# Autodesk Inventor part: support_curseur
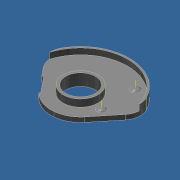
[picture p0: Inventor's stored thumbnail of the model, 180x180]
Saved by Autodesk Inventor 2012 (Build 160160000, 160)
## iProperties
Created: 2011-07
Part Number: support_curseur
Document SubType Name: Modeling
Designer: didierf
Density: 1.4 g/cm^3
Material: PVC-U
Mass: 0.16648 g
Surface Area: 3.90351 cm^2
Volume: 0.118915 cm^3
Author: didierf
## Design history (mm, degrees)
sketch "Esquisse3"
  geometry: L1 (-14.379, 11.345)-(1.25, 18.566); L2 (1.25, 18.566)-(10.479, -1.409); L3 (10.479, -1.409)-(-5.149, -8.63); L4 (-5.149, -8.63)-(-14.379, 11.345); L5 (4.506, -11.411)-(4.506, -32.563); 1 other entity
  constraints: 2 end point, 1 vertical, 2 other
  dimensions: "d19" = 17.216 distance of L1.start L1.end; "d84" = 24.7991 deg angle of L5 L4
  node "Image2"
sketch "tracé"
  geometry: L1 (3.886, -3.147)-(6.941, 0.626); L2 (0, -41.976)-(0, 8.25); L3 (-3.534, -3.184)-(-5.423, -0.851); L4 (-5.774, -0.814)-(-6.941, 0.626); L5 (0, 0)-(-3.552, -3.519); C1 r 2.5 at (0, 0); C2 r 0.5 at (4.25, -0.7); C3 r 0.5 at (4.25, 5.1); C4 r 2.95 at (0, 0); C5 r 1 at (3, 4); A1 r 5 centre (0, 0) between (-3.552, -3.519) and (3.886, -3.147); A2 r 8.25 centre (0, 0) between (7.243, 3.95) and (-7.243, 3.95); A3 r 3 centre (-4.609, 2.514) between (-7.243, 3.95) and (-6.941, 0.626); A4 r 3 centre (4.609, 2.514) between (6.941, 0.626) and (7.243, 3.95); A5 r 0.25 centre (-3.728, -3.341) between (-3.552, -3.519) and (-3.534, -3.184); A6 r 0.25 centre (-5.617, -1.009) between (-5.423, -0.851) and (-5.774, -0.814); A7 r 7.95 centre (0, 0) between (7.603, 2.323) and (-7.603, 2.323); 1 further point
  constraints: 17 point on circle, 12 centre point, 10 end point, 9 tangent, 5 coincident, 1 parallel, 1 point on line, 1 vertical
  dimensions: "d53" = 10 diameter of A1; "d54" = 5 diameter of C1; "d57" = 8.25 radius of A2; "d60" = 6 diameter of A3; "d61" = 6 diameter of A4; "d66" = 78 deg angle of L1 L4; "d67" = 0.25 radius of A5; "d68" = 0.25 radius of A6; "d69" = 0.25 distance between parallel lines of L4 L3; "d70" = 3.5 distance of L4.start L5.end; "d71" = 39 deg angle of L1 L2 (derived); "d104" = 1 diameter of C2; "d105" = 1 diameter of C3; "d106" = 4.25 horizontal distance of C2.centre point (0, 0); "d107" = 0.7 vertical distance of C2.centre point (0, 0); "d108" = 5.8 distance of C2.centre C3.centre; "d109" = 4.25 horizontal distance of C3.centre point (0, 0) (derived); "d110" = 0.3 radial gap between concentric circles of A7 A2; "d114" = 5.9 diameter of C4; "d115" = 2 diameter of C5; "d117" = 3 distance from line of C5.centre L2; "d120" = 4 vertical distance of C5.centre point (0, 0)
extrude "embase" new body sketch "tracé" distance "d122" = 0.8; taper "d123" = 0 deg
extrude "bossage central" join sketch "tracé" distance "d124" = 1.2; taper "d125" = 0 deg
extrude "plotSertissage1" join sketch "tracé" distance "d126" = 1; taper "d127" = 0 deg
extrude "plotSertissage2" join sketch "tracé" distance "d128" = 0.1; taper "d129" = 0 deg
node "Plan de construction1"
  node "Axe de construction1"
  node "Axe de construction2"
sketch "sertissage"
  geometry: L1 (-1.2, 5.8)-(1.6, 5.8) reference; L2 (0.1, 6.3)-(0.1, 5.3) reference; L3 (0.4, 4.925)-(0.4, 6.54); L4 (0.1, 5.05)-(0.1, 6.55); L5 (0.1, 0.5)-(0.1, -0.5) reference; L6 (0.4, 1.009)-(0.4, -1.186); L7 (-1.2, 0)-(1.6, 0) reference; L8 (0.1, 0)-(0.1, -0.75); L9 (0.1, 0)-(0.1, 0.75); L10 (0.4, 5.8)-(0.1, 5.8); L11 (0.4, 0)-(0.1, 0); A1 r 1.088 centre (-0.687, 5.8) between (0.1, 5.05) and (0.4, 5.8); A2 r 1.088 centre (-0.688, 0) between (0.1, -0.75) and (0.4, 0)
  constraints: 14 end point, 7 point on line, 4 point on circle, 3 parallel, 2 centre point, 2 collinear, 2 midpoint
  dimensions: "d130" = 0.3 distance between parallel lines of L2 L3; "d131" = 0.75 distance from line of L4.start L1; "d132" = 1.5 distance of L4.start L4.end; "d133" = 1.0875 radius of A1; "d134" = 0.3 distance between parallel lines of L6 L5 (derived); "d135" = 0.75 distance of L8.start L8.end; "d136" = 0.75 distance of L8.start L9.end; "d137" = 1.0875 radius of A2
revolve "plot1" stored, may be unused: angle "d138" = 90 deg
revolve "plot2" stored, may be unused: angle "d139" = 90 deg
node "Plan de construction2"
extrude "plot3" join sketch "tracé" stored distance "d141" = 0.1; taper "d142" = 0 deg
node "Solide1"
node "Corps solides"
node "Corps surfaciques"
fillet "congé" dims "d143" = 0.5
other parameters: "d52" = 78 deg, "d62" = 0.25, "d63" = 0.25, "d140" = -3.2
